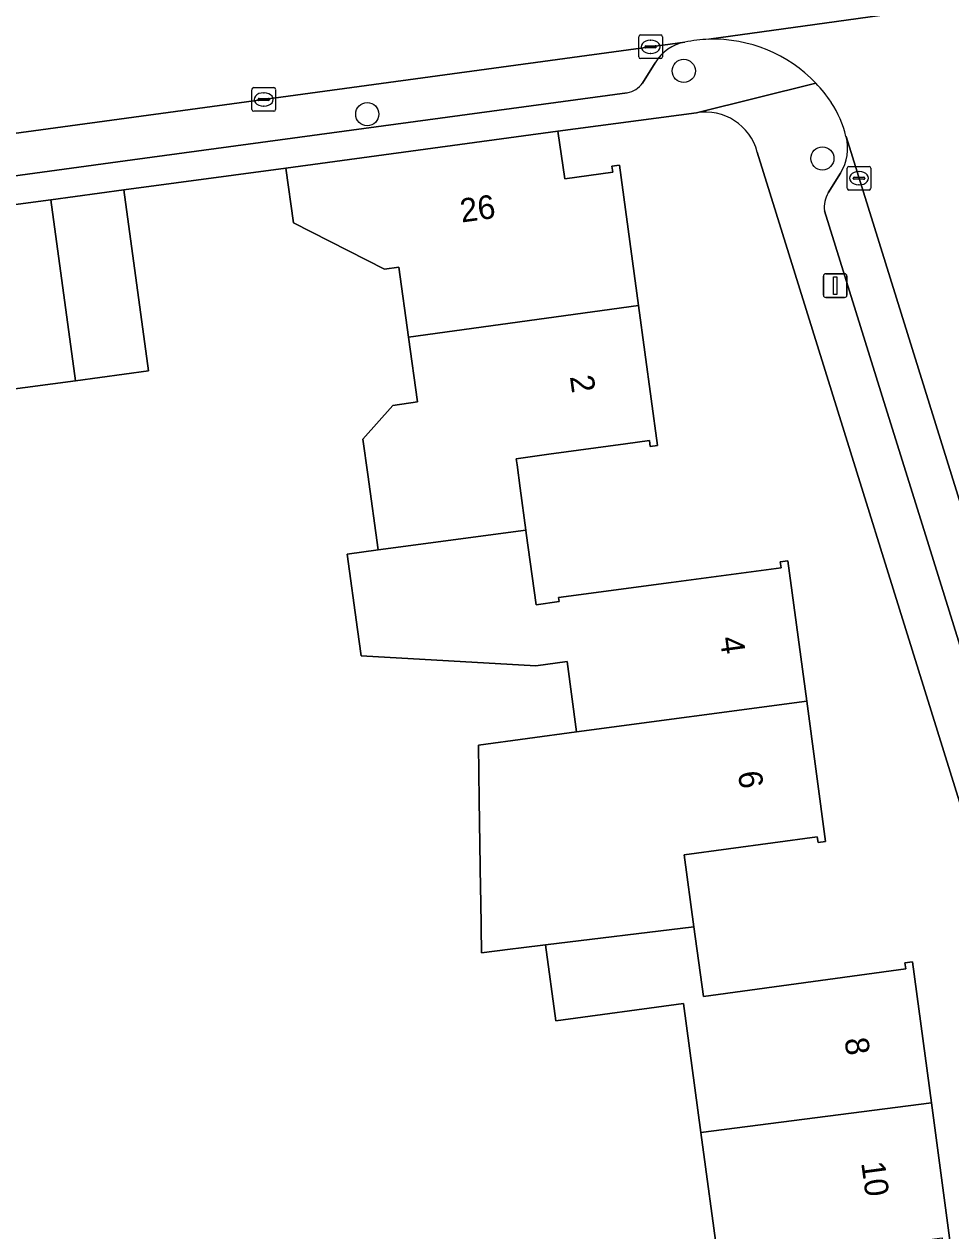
# Model space of a CAD drawing. Extents: x 163426 to 164192, y 380329 to 381641.
# Drawn here: x 163631.8 to 163670.9, y 381058.2 to 381109.2 of the extents above; entities that cross this region are included whole.
import ezdxf

# ---------------------------------------------------------------- set-up
doc = ezdxf.new("R2010")
doc.units = 0
for name, color, linetype in [('IMGEO_Boom', 7, 'Continuous'), ('IMGEO_Erf', 7, 'Continuous'), ('IMGEO_Kolk', 7, 'Continuous'), ('IMGEO_Lichtmast', 7, 'Continuous'), ('IMGEO_Muur', 7, 'Continuous'), ('IMGEO_Pand', 7, 'Continuous'), ('IMGEO_Pand_nummerreeks', 7, 'Continuous'), ('IMGEO_Parkeervlak_open', 7, 'Continuous'), ('IMGEO_Rijbaan_lokaal_open', 7, 'Continuous'), ('IMGEO_Voetpad_open', 7, 'Continuous')]:
    doc.layers.add(name, color=color, linetype=linetype)

msp = doc.modelspace()

# ---------------------------------------------------------------- linework, layer by layer
at = {"layer": 'IMGEO_Boom'}
for centre in [(163659.616, 381107.216), (163646.255, 381105.387), (163665.465, 381103.517)]:
    msp.add_circle(centre, 0.489, dxfattribs=at)
at = {"layer": 'IMGEO_Erf'}
for points in [[(163660.157, 381105.447), (163654.299, 381104.673), (163654.588, 381102.658), (163656.615, 381102.938), (163656.582, 381103.188), (163656.899, 381103.231), (163657.708, 381097.304), (163658.513, 381091.4), (163658.196, 381091.357), (163658.162, 381091.605), (163657.162, 381091.468), (163653.922, 381091.026), (163652.54, 381090.837), (163652.576, 381090.572), (163652.709, 381089.599), (163652.953, 381087.812), (163652.969, 381087.697), (163653.382, 381084.67), (163654.352, 381084.804), (163654.33, 381084.971), (163659.085, 381085.61), (163663.723, 381086.234), (163663.69, 381086.482), (163664.007, 381086.525), (163664.804, 381080.597), (163665.601, 381074.668), (163665.284, 381074.625), (163665.25, 381074.872), (163659.629, 381074.106), (163660.045, 381071.06), (163660.445, 381068.128), (163668.985, 381069.294), (163668.952, 381069.543), (163669.269, 381069.586), (163670.07, 381063.639), (163670.866, 381057.722)], [(163603.447, 381095.786), (163603.525, 381095.083), (163616.544, 380999.748), (163619.246, 380999.933), (163622.549, 381000.159), (163633.697, 381000.898), (163646.569, 381001.751), (163692.559, 381007.908), (163662.718, 381103.781)], [(163660.34, 381062.378), (163659.608, 381067.824), (163654.214, 381067.099), (163653.784, 381070.3), (163652.747, 381070.174), (163652.289, 381070.118), (163651.083, 381069.972), (163651.049, 381072.154), (163651.041, 381072.671), (163650.983, 381076.425), (163650.947, 381078.739), (163655.092, 381079.303), (163654.692, 381082.278), (163653.364, 381082.095), (163646.001, 381082.507), (163645.846, 381083.629), (163645.408, 381086.804), (163646.713, 381086.984), (163646.273, 381090.169), (163646.067, 381091.658), (163647.339, 381093.081), (163648.37, 381093.235), (163647.993, 381095.963), (163647.584, 381098.924), (163646.981, 381098.841), (163643.14, 381100.791), (163642.822, 381103.109), (163635.974, 381102.194), (163637.017, 381094.551), (163633.937, 381094.131), (163630.858, 381093.711)], [(163661.079, 381056.887), (163660.34, 381062.378)]]:
    msp.add_lwpolyline(points, dxfattribs=at)
msp.add_arc((163660.52, 381103.204), 2.272, 14.7033, 99.2065, dxfattribs=at)
at = {"layer": 'IMGEO_Kolk'}
for p, q in [((163657.79, 381108.732), (163658.642, 381108.732)), ((163657.715, 381107.806), (163657.715, 381108.658)), ((163657.974, 381108.226), (163657.974, 381108.238)), ((163658.017, 381108.275), (163658.415, 381108.275)), ((163658.203, 381108.512), (163658.228, 381108.512)), ((163658.458, 381108.238), (163658.458, 381108.226)), ((163658.716, 381108.658), (163658.716, 381107.806)), ((163658.642, 381107.732), (163657.79, 381107.732)), ((163658.412, 381108.189), (163658.014, 381108.189)), ((163658.226, 381107.952), (163658.201, 381107.952)), ((163641.386, 381105.584), (163641.386, 381106.436)), ((163641.461, 381106.51), (163642.313, 381106.51)), ((163641.874, 381106.29), (163641.899, 381106.29)), ((163642.387, 381106.436), (163642.387, 381105.584)), ((163641.645, 381106.004), (163641.645, 381106.016)), ((163642.083, 381105.967), (163641.685, 381105.967)), ((163641.688, 381106.053), (163642.086, 381106.053)), ((163641.897, 381105.73), (163641.872, 381105.73)), ((163642.129, 381106.016), (163642.129, 381106.004)), ((163642.313, 381105.51), (163641.461, 381105.51)), ((163666.51, 381102.255), (163666.51, 381103.107)), ((163666.585, 381103.181), (163667.437, 381103.181)), ((163667.511, 381103.107), (163667.511, 381102.255)), ((163666.769, 381102.675), (163666.769, 381102.687)), ((163667.207, 381102.638), (163666.809, 381102.638)), ((163666.812, 381102.724), (163667.21, 381102.724)), ((163666.998, 381102.961), (163667.023, 381102.961)), ((163667.253, 381102.687), (163667.253, 381102.675)), ((163667.437, 381102.181), (163666.585, 381102.181)), ((163667.021, 381102.401), (163666.996, 381102.401))]:
    msp.add_line(p, q, dxfattribs=at)
for points in [[(163657.79, 381108.732), (163658.642, 381108.732)], [(163657.715, 381107.806), (163657.715, 381108.658)], [(163658.716, 381108.658), (163658.716, 381107.806)], [(163658.642, 381107.732), (163657.79, 381107.732)], [(163641.386, 381105.584), (163641.386, 381106.436)], [(163641.461, 381106.51), (163642.313, 381106.51)], [(163642.387, 381106.436), (163642.387, 381105.584)], [(163642.313, 381105.51), (163641.461, 381105.51)], [(163666.51, 381102.255), (163666.51, 381103.107)], [(163666.585, 381103.181), (163667.437, 381103.181)], [(163667.511, 381103.107), (163667.511, 381102.255)], [(163667.437, 381102.181), (163666.585, 381102.181)]]:
    msp.add_lwpolyline(points, dxfattribs=at)
for centre, radius, start, end in [((163657.792, 381108.656), 0.0765, 91.552, 178.448), ((163657.792, 381108.656), 0.0765, 91.552, 178.448), ((163658.64, 381108.656), 0.0765, 1.552, 88.448), ((163658.64, 381108.656), 0.0765, 1.552, 88.448), ((163658.014, 381108.235), 0.0403, 85.8775, 175.7526), ((163658.011, 381108.225), 0.0366, 178.938, 274.7102), ((163658.415, 381108.232), 0.043, 264.8664, 352.4533), ((163658.419, 381108.237), 0.0386, 1.7309, 96.639), ((163657.792, 381107.808), 0.0765, 181.552, 268.448), ((163657.792, 381107.808), 0.0765, 181.552, 268.448), ((163658.64, 381107.808), 0.0765, 271.552, 358.448), ((163658.64, 381107.808), 0.0765, 271.552, 358.448), ((163641.463, 381106.434), 0.0765, 91.552, 178.448), ((163641.463, 381106.434), 0.0765, 91.552, 178.448), ((163642.311, 381106.434), 0.0765, 1.552, 88.448), ((163642.311, 381106.434), 0.0765, 1.552, 88.448), ((163641.685, 381106.013), 0.0403, 85.8775, 175.7526), ((163641.682, 381106.003), 0.0366, 178.938, 274.7102), ((163642.086, 381106.01), 0.043, 264.8664, 352.4533), ((163642.09, 381106.015), 0.0386, 1.7309, 96.639), ((163641.463, 381105.586), 0.0765, 181.552, 268.448), ((163641.463, 381105.586), 0.0765, 181.552, 268.448), ((163642.311, 381105.586), 0.0765, 271.552, 358.448), ((163642.311, 381105.586), 0.0765, 271.552, 358.448), ((163666.587, 381103.105), 0.0765, 91.552, 178.448), ((163666.587, 381103.105), 0.0765, 91.552, 178.448), ((163667.435, 381103.105), 0.0765, 1.552, 88.448), ((163667.435, 381103.105), 0.0765, 1.552, 88.448), ((163666.809, 381102.684), 0.0403, 85.8775, 175.7526), ((163666.806, 381102.674), 0.0366, 178.938, 274.7102), ((163667.21, 381102.681), 0.043, 264.8664, 352.4533), ((163667.214, 381102.686), 0.0386, 1.7309, 96.639), ((163666.587, 381102.257), 0.0765, 181.552, 268.448), ((163666.587, 381102.257), 0.0765, 181.552, 268.448), ((163667.435, 381102.257), 0.0765, 271.552, 358.448), ((163667.435, 381102.257), 0.0765, 271.552, 358.448)]:
    msp.add_arc(centre, radius, start, end, dxfattribs=at)
for centre, major_axis, ratio, start_param, end_param in [((163658.202, 381108.232), (-0.387, 0.002), 0.722429, 4.712389, 7.853982), ((163658.227, 381108.232), (-0.39, 0.002), 0.717154, 1.570796, 4.712389), ((163641.873, 381106.01), (-0.387, 0.002), 0.722429, 4.712389, 7.853982), ((163641.898, 381106.01), (-0.39, 0.002), 0.717154, 1.570796, 4.712389), ((163666.997, 381102.681), (-0.387, 0.002), 0.722429, 4.712389, 7.853982), ((163667.022, 381102.681), (-0.39, 0.002), 0.717154, 1.570796, 4.712389)]:
    msp.add_ellipse(centre, major_axis=major_axis, ratio=ratio, start_param=start_param, end_param=end_param, dxfattribs=at)
at = {"layer": 'IMGEO_Lichtmast'}
for p, q in [((163665.51, 381097.745), (163665.51, 381098.545)), ((163665.51, 381098.545), (163665.51, 381097.745)), ((163665.61, 381098.645), (163666.4, 381098.645)), ((163666.4, 381098.645), (163665.61, 381098.645)), ((163666.5, 381098.545), (163666.5, 381097.745)), ((163666.5, 381097.745), (163666.5, 381098.545)), ((163666.4, 381097.645), (163665.61, 381097.645)), ((163665.61, 381097.645), (163666.4, 381097.645))]:
    msp.add_line(p, q, dxfattribs=at)
msp.add_lwpolyline([(163665.93, 381098.52), (163666.08, 381098.52), (163666.08, 381097.77), (163665.93, 381097.77), (163665.93, 381098.52)], dxfattribs=at)
for centre, start, end in [((163665.61, 381098.545), 90, 180), ((163665.61, 381098.545), 90, 180), ((163666.4, 381098.545), 0, 90), ((163666.4, 381098.545), 360, 90), ((163665.61, 381097.745), 180, 270), ((163665.61, 381097.745), 180, 270), ((163666.4, 381097.745), 270, 0), ((163666.4, 381097.745), 270, 0)]:
    msp.add_arc(centre, 0.1, start, end, dxfattribs=at)
at = {"layer": 'IMGEO_Muur'}
msp.add_lwpolyline([(163642.822, 381103.109), (163635.974, 381102.194)], dxfattribs=at)
at = {"layer": 'IMGEO_Pand'}
for points in [[(163647.993, 381095.963), (163657.708, 381097.304), (163656.899, 381103.231), (163656.582, 381103.188), (163656.615, 381102.938), (163654.588, 381102.658), (163654.299, 381104.673), (163642.822, 381103.109), (163643.14, 381100.791), (163646.981, 381098.841), (163647.584, 381098.924)], [(163632.895, 381101.774), (163633.937, 381094.131), (163637.017, 381094.551), (163635.974, 381102.194)], [(163632.895, 381101.774), (163629.816, 381101.354), (163630.858, 381093.711), (163633.937, 381094.131)], [(163653.922, 381091.026), (163657.162, 381091.468), (163658.162, 381091.605), (163658.196, 381091.357), (163658.513, 381091.4), (163657.708, 381097.304), (163647.993, 381095.963), (163648.37, 381093.235), (163647.339, 381093.081), (163646.067, 381091.658), (163646.273, 381090.169), (163646.713, 381086.984), (163652.953, 381087.812), (163652.709, 381089.599), (163652.576, 381090.572), (163652.54, 381090.837)], [(163646.713, 381086.984), (163645.408, 381086.804), (163645.846, 381083.629), (163646.001, 381082.507), (163653.364, 381082.095), (163654.692, 381082.278), (163655.092, 381079.303), (163664.804, 381080.597), (163664.007, 381086.525), (163663.69, 381086.482), (163663.723, 381086.234), (163659.085, 381085.61), (163654.33, 381084.971), (163654.352, 381084.804), (163653.382, 381084.67), (163652.969, 381087.697), (163652.953, 381087.812)], [(163665.25, 381074.872), (163665.284, 381074.625), (163665.601, 381074.668), (163664.804, 381080.597), (163655.092, 381079.303), (163650.947, 381078.739), (163650.983, 381076.425), (163651.041, 381072.671), (163651.049, 381072.154), (163651.083, 381069.972), (163652.289, 381070.118), (163652.747, 381070.174), (163653.784, 381070.3), (163660.045, 381071.06), (163659.629, 381074.106)], [(163669.269, 381069.586), (163668.952, 381069.543), (163668.985, 381069.294), (163660.445, 381068.128), (163660.045, 381071.06), (163653.784, 381070.3), (163654.214, 381067.099), (163659.608, 381067.824), (163660.34, 381062.378), (163670.07, 381063.639)], [(163665.29, 381054.187), (163664.892, 381057.181), (163670.515, 381057.928), (163670.549, 381057.679), (163670.866, 381057.722), (163670.07, 381063.639), (163660.34, 381062.378), (163661.079, 381056.887), (163658.604, 381056.554), (163655.335, 381056.114), (163655.763, 381052.929), (163659.034, 381053.357)]]:
    msp.add_lwpolyline(points, close=True, dxfattribs=at)
at = {"layer": 'IMGEO_Parkeervlak_open'}
for points in [[(163659.662, 381108.43), (163606.824, 381101.24)], [(163657.872, 381106.698), (163658.405, 381107.557)], [(163608.303, 381100.787), (163609.06, 381100.144), (163609.389, 381099.954), (163609.77, 381099.849), (163629.639, 381102.547), (163636.344, 381103.458), (163657.229, 381106.294)], [(163697.932, 381003.337), (163666.463, 381104.446)], [(163666.233, 381102.898), (163665.716, 381102.063)], [(163665.558, 381101.299), (163667.938, 381093.654), (163669.956, 381087.172), (163673.323, 381076.358), (163675.341, 381069.878), (163678.617, 381059.355), (163680.63, 381052.891), (163683.903, 381042.378), (163685.923, 381035.891), (163689.196, 381025.38), (163691.21, 381018.912), (163695.441, 381005.322)]]:
    msp.add_lwpolyline(points, dxfattribs=at)
for centre, radius, start, end in [((163659.992, 381106.613), 1.846, 100.2981, 149.2627), ((163657.038, 381107.312), 1.035, 280.6278, 323.6549), ((163664.568, 381103.936), 1.962, 328.0462, 15.0516), ((163666.692, 381101.463), 1.146, 148.4111, 188.2201)]:
    msp.add_arc(centre, radius, start, end, dxfattribs=at)
at = {"layer": 'IMGEO_Rijbaan_lokaal_open'}
for points in [[(163676.785, 381115.879), (163673.521, 381115.447), (163669.804, 381114.955), (163667.226, 381114.614), (163663.45, 381114.088), (163632.364, 381109.879), (163629.549, 381109.438), (163625.771, 381108.926), (163605.902, 381106.231), (163606.564, 381101.2), (163606.824, 381101.24), (163659.662, 381108.43)], [(163660.678, 381108.549), (163676.836, 381110.807), (163679.071, 381111.11)], [(163676.836, 381110.807), (163660.678, 381108.549)], [(163666.463, 381104.446), (163697.932, 381003.337), (163698.985, 381000), (163699.868, 380997.203), (163700.021, 380996.72), (163702.182, 380989.782), (163702.796, 380987.787), (163702.975, 380987.284)]]:
    msp.add_lwpolyline(points, dxfattribs=at)
for centre, radius, start, end in [((163660.874, 381102.482), 6.07, 91.8469, 101.5139), ((163660.864, 381102.577), 5.975, 43.6353, 91.7796), ((163660.912, 381102.615), 5.914, 33.4902, 43.6933), ((163661.728, 381103.249), 4.883, 14.1858, 32.5682)]:
    msp.add_arc(centre, radius, start, end, dxfattribs=at)
at = {"layer": 'IMGEO_Voetpad_open'}
for points in [[(163658.405, 381107.557), (163657.872, 381106.698)], [(163629.816, 381101.354), (163632.895, 381101.774), (163635.974, 381102.194), (163642.822, 381103.109), (163654.299, 381104.673), (163660.157, 381105.447), (163665.188, 381106.7)], [(163665.188, 381106.7), (163660.157, 381105.447)], [(163657.229, 381106.294), (163636.344, 381103.458), (163629.639, 381102.547), (163609.77, 381099.849), (163609.389, 381099.954), (163609.06, 381100.144), (163608.303, 381100.787)], [(163662.718, 381103.781), (163692.559, 381007.908), (163693.735, 381004.13), (163694.045, 381003.135), (163695.021, 381000), (163696.258, 380996.026), (163696.15, 380996.012), (163694.251, 380995.378), (163694.565, 380994.346), (163692.034, 380992.86), (163686.717, 380989.739), (163687.932, 380987.632), (163692.566, 380990.347)], [(163665.716, 381102.063), (163666.233, 381102.898)], [(163689.196, 381025.38), (163685.923, 381035.891), (163683.903, 381042.378), (163680.63, 381052.891), (163678.617, 381059.355), (163675.341, 381069.878), (163673.323, 381076.358), (163669.956, 381087.172), (163667.938, 381093.654), (163665.558, 381101.299)]]:
    msp.add_lwpolyline(points, dxfattribs=at)
for centre, radius, start, end in [((163659.992, 381106.613), 1.846, 100.2981, 149.2627), ((163660.874, 381102.482), 6.07, 91.8469, 101.5139), ((163660.864, 381102.577), 5.975, 43.6353, 91.7796), ((163657.038, 381107.312), 1.035, 280.6278, 323.6549), ((163660.912, 381102.615), 5.914, 33.4902, 43.6933), ((163661.728, 381103.249), 4.883, 14.1858, 32.5682), ((163660.52, 381103.204), 2.272, 14.7033, 99.2065), ((163664.568, 381103.936), 1.962, 328.0462, 15.0516), ((163666.692, 381101.463), 1.146, 148.4111, 188.2201)]:
    msp.add_arc(centre, radius, start, end, dxfattribs=at)

# ---------------------------------------------------------------- texts
at = {"layer": 'IMGEO_Pand_nummerreeks'}
for s, rotation, p in [('26', 7.76, (163650.238, 381100.809)), ('2', 277.7691, (163654.806, 381094.308)), ('4', 277.6567, (163661.135, 381083.272)), ('6', 277.6545, (163661.899, 381077.592)), ('8', 277.666, (163666.398, 381066.328)), ('10', 277.6664, (163667.102, 381061.1))]:
    msp.add_text(s, height=1, rotation=rotation, dxfattribs=at).set_placement(p)

doc.saveas('drawing.dxf')
